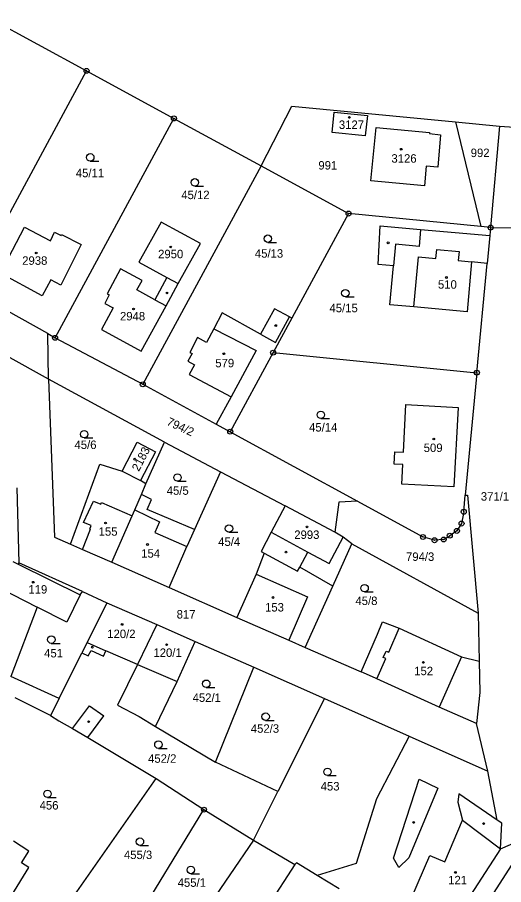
# Model space of a CAD drawing. Extents: x -735249 to -729401, y -1124843 to -1121828.
# Drawn here: x -734537.4 to -734439.6, y -1122803 to -1122628.7 of the extents above; entities that cross this region are included whole.
import ezdxf

# ---------------------------------------------------------------- set-up
doc = ezdxf.new("R2010")
doc.units = 0
for name, color, linetype in [('Vrstva 1', 7, 'Continuous'), ('Vrstva 13', 7, 'Continuous'), ('Vrstva 18', 7, 'Continuous'), ('Vrstva 19', 7, 'Continuous'), ('Vrstva 25', 7, 'Continuous'), ('Vrstva 4', 7, 'Continuous')]:
    doc.layers.add(name, color=color, linetype=linetype)

msp = doc.modelspace()

# ---------------------------------------------------------------- linework, layer by layer
at = {"layer": 'Vrstva 1'}
for points in [[(-734547.14, -1122683.19), (-734523.44, -1122639.42)], [(-734474.05, -1122651.8), (-734473.65, -1122647.74)], [(-734473.65, -1122647.74), (-734466.97, -1122648.39)], [(-734529.77, -1122693.08), (-734505.87, -1122648.98)], [(-734466.97, -1122648.39), (-734467.41, -1122652.45)], [(-734449.25, -1122649.69), (-734444.16, -1122670.72)], [(-734466.26, -1122661.51), (-734465.21, -1122650.81)], [(-734465.21, -1122650.81), (-734454.5, -1122651.83)], [(-734440.39, -1122650.54), (-734442.18, -1122670.92)], [(-734467.41, -1122652.45), (-734474.05, -1122651.8)], [(-734454.5, -1122651.83), (-734454.5, -1122652.02)], [(-734454.5, -1122652.02), (-734452.25, -1122652.3)], [(-734452.25, -1122652.3), (-734452.82, -1122658.76)], [(-734488.31, -1122658.54), (-734512.13, -1122702.42)], [(-734488.31, -1122658.54), (-734470.74, -1122668.1)], [(-734455.12, -1122658.57), (-734455.5, -1122662.53)], [(-734452.82, -1122658.76), (-734455.12, -1122658.57)], [(-734455.5, -1122662.53), (-734466.26, -1122661.51)], [(-734470.74, -1122668.1), (-734482.16, -1122689.14)], [(-734444.16, -1122670.72), (-734470.74, -1122668.1)], [(-734508.45, -1122669.82), (-734512.93, -1122677.86)], [(-734500.54, -1122674.09), (-734508.45, -1122669.82)], [(-734464.82, -1122678.34), (-734464.37, -1122670.58)], [(-734464.37, -1122670.58), (-734456.27, -1122671.28)], [(-734442.18, -1122670.92), (-734444.16, -1122670.72)], [(-734540.77, -1122680.09), (-734535.9, -1122670.83)], [(-734535.9, -1122670.83), (-734530.69, -1122673.58)], [(-734530.69, -1122673.58), (-734529.91, -1122671.87)], [(-734529.91, -1122671.87), (-734528.58, -1122672.51)], [(-734528.58, -1122672.51), (-734528.48, -1122672.34)], [(-734528.48, -1122672.34), (-734524.51, -1122674.3)], [(-734456.27, -1122671.28), (-734442.33, -1122672.48)], [(-734442.33, -1122672.48), (-734442.87, -1122678.13)], [(-734442.18, -1122670.92), (-734442.33, -1122672.48)], [(-734442.18, -1122670.92), (-734432.18, -1122671.05)], [(-734505, -1122682.19), (-734500.54, -1122674.09)], [(-734524.51, -1122674.3), (-734528.62, -1122682.51)], [(-734516.61, -1122679.23), (-734519.28, -1122684.26)], [(-734512.26, -1122681.53), (-734516.61, -1122679.23)], [(-734512.93, -1122677.86), (-734507.29, -1122680.93)], [(-734461.72, -1122678.61), (-734464.82, -1122678.34)], [(-734462.43, -1122686.42), (-734461.72, -1122678.61)], [(-734446.02, -1122677.83), (-734446.9, -1122687.85)], [(-734442.87, -1122678.13), (-734446.02, -1122677.83)], [(-734444.95, -1122700.08), (-734442.87, -1122678.13)], [(-734532.4, -1122684.64), (-734540.77, -1122680.09)], [(-734507.29, -1122680.93), (-734509.74, -1122685.41)], [(-734530.64, -1122681.41), (-734532.4, -1122684.64)], [(-734528.62, -1122682.51), (-734530.64, -1122681.41)], [(-734513.31, -1122683.44), (-734512.26, -1122681.53)], [(-734507.46, -1122686.66), (-734505, -1122682.19)], [(-734518.91, -1122684.45), (-734519.77, -1122686.17)], [(-734519.28, -1122684.26), (-734518.91, -1122684.45)], [(-734509.74, -1122685.41), (-734513.31, -1122683.44)], [(-734519.77, -1122686.17), (-734518.1, -1122687.06)], [(-734509.74, -1122685.41), (-734507.46, -1122686.66)], [(-734457.62, -1122686.86), (-734462.43, -1122686.42)], [(-734531.21, -1122692.22), (-734539.28, -1122687.73)], [(-734518.1, -1122687.06), (-734520.43, -1122691.38)], [(-734512.48, -1122695.77), (-734507.46, -1122686.66)], [(-734496.15, -1122688.07), (-734497.86, -1122691.26)], [(-734488.43, -1122692.37), (-734496.15, -1122688.07)], [(-734485.67, -1122687.24), (-734488.43, -1122692.37)], [(-734482.65, -1122688.88), (-734485.67, -1122687.24)], [(-734446.9, -1122687.85), (-734457.62, -1122686.86)], [(-734482.16, -1122689.14), (-734485.92, -1122696.06)], [(-734482.16, -1122689.14), (-734482.65, -1122688.88)], [(-734520.43, -1122691.38), (-734512.48, -1122695.77)], [(-734497.86, -1122691.26), (-734499.32, -1122693.99)], [(-734531.09, -1122701.37), (-734531.21, -1122692.22)], [(-734531.21, -1122692.22), (-734529.77, -1122693.08)], [(-734529.77, -1122693.08), (-734512.13, -1122702.42)], [(-734501.11, -1122693.03), (-734502.64, -1122696.01)], [(-734499.32, -1122693.99), (-734501.11, -1122693.03)], [(-734531.09, -1122701.37), (-734539.43, -1122696.77)], [(-734502.22, -1122696.24), (-734503.07, -1122697.78)], [(-734502.64, -1122696.01), (-734502.22, -1122696.24)], [(-734485.92, -1122696.06), (-734494.54, -1122711.94)], [(-734485.92, -1122696.06), (-734444.95, -1122700.08)], [(-734503.07, -1122697.78), (-734501.74, -1122698.5)], [(-734501.74, -1122698.5), (-734502.78, -1122700.43)], [(-734502.78, -1122700.43), (-734494.38, -1122704.95)], [(-734444.95, -1122700.08), (-734447.27, -1122724.73)], [(-734507.74, -1122714.08), (-734531.09, -1122701.37)], [(-734531.09, -1122701.37), (-734529.88, -1122733.15)], [(-734512.13, -1122702.42), (-734497.35, -1122710.42)], [(-734494.38, -1122704.95), (-734497.35, -1122710.42)], [(-734459.7, -1122716.07), (-734459.22, -1122706.49)], [(-734459.22, -1122706.49), (-734448.71, -1122707.11)], [(-734448.71, -1122707.11), (-734449.57, -1122723.04)], [(-734497.35, -1122710.42), (-734494.54, -1122711.94)], [(-734494.54, -1122711.94), (-734468.96, -1122725.91)], [(-734516.28, -1122719.89), (-734513.27, -1122714.06)], [(-734513.27, -1122714.06), (-734509.58, -1122715.96)], [(-734511.54, -1122722.39), (-734507.74, -1122714.08)], [(-734507.74, -1122714.08), (-734496.52, -1122720.03)], [(-734509.58, -1122715.96), (-734512.57, -1122721.75)], [(-734461.55, -1122718.45), (-734461.43, -1122715.99)], [(-734461.43, -1122715.99), (-734459.7, -1122716.07)], [(-734526.64, -1122734.56), (-734520.75, -1122718.45)], [(-734520.75, -1122718.45), (-734516.28, -1122719.89)], [(-734459.82, -1122718.53), (-734461.55, -1122718.45)], [(-734460.02, -1122722.48), (-734459.82, -1122718.53)], [(-734516.28, -1122719.89), (-734512.57, -1122721.75)], [(-734496.52, -1122720.03), (-734501.72, -1122731.57)], [(-734496.52, -1122720.03), (-734483.48, -1122726.85)], [(-734511.54, -1122722.39), (-734512.57, -1122721.75)], [(-734512.39, -1122724.55), (-734511.54, -1122722.39)], [(-734449.57, -1122723.04), (-734460.02, -1122722.48)], [(-734537.44, -1122723.23), (-734537.08, -1122738.3)], [(-734513.7, -1122727.63), (-734512.39, -1122724.55)], [(-734510.41, -1122725.56), (-734512.39, -1122724.55)], [(-734447.58, -1122728.03), (-734447.27, -1122724.73)], [(-734447.27, -1122724.73), (-734446.8, -1122724.71)], [(-734446.8, -1122724.71), (-734444.66, -1122748.41)], [(-734511.28, -1122727.58), (-734510.41, -1122725.56)], [(-734472.72, -1122726.12), (-734473.53, -1122732.13)], [(-734468.96, -1122725.91), (-734472.72, -1122726.12)], [(-734468.96, -1122725.91), (-734455.79, -1122733.1)], [(-734514.27, -1122728.86), (-734513.7, -1122727.63)], [(-734501.72, -1122731.57), (-734511.28, -1122727.58)], [(-734483.48, -1122726.85), (-734486.29, -1122732.15)], [(-734473.53, -1122732.13), (-734483.48, -1122726.85)], [(-734447.58, -1122728.03), (-734448.03, -1122730.4)], [(-734518.34, -1122738.18), (-734514.27, -1122728.86)], [(-734501.72, -1122731.57), (-734503.27, -1122735)], [(-734448.03, -1122730.4), (-734448.96, -1122731.87)], [(-734529.88, -1122733.15), (-734526.64, -1122734.56)], [(-734486.29, -1122732.15), (-734488.35, -1122736.04)], [(-734471.86, -1122733.15), (-734473.53, -1122732.13)], [(-734470.09, -1122734.45), (-734471.86, -1122733.15)], [(-734453.45, -1122733.75), (-734455.79, -1122733.1)], [(-734451.63, -1122733.61), (-734450.39, -1122732.84)], [(-734448.96, -1122731.87), (-734450.39, -1122732.84)], [(-734526.64, -1122734.56), (-734524.29, -1122735.59)], [(-734506.84, -1122743.27), (-734503.27, -1122735)], [(-734473.93, -1122742.99), (-734470.09, -1122734.45)], [(-734470.09, -1122734.45), (-734444.66, -1122748.41)], [(-734451.63, -1122733.61), (-734453.45, -1122733.75)], [(-734524.29, -1122735.59), (-734518.34, -1122738.18)], [(-734487.75, -1122736.36), (-734489.34, -1122740.55)], [(-734488.35, -1122736.04), (-734487.75, -1122736.36)], [(-734487.75, -1122736.36), (-734481, -1122739.99)], [(-734538.26, -1122738.04), (-734537.07, -1122738.63)], [(-734537.07, -1122738.63), (-734537.08, -1122738.3)], [(-734524.26, -1122744.09), (-734537.08, -1122738.3)], [(-734518.34, -1122738.18), (-734506.84, -1122743.27)], [(-734481, -1122739.99), (-734480.56, -1122739.17)], [(-734473.93, -1122742.99), (-734480.56, -1122739.17)], [(-734489.34, -1122740.55), (-734493.22, -1122749.27)], [(-734506.84, -1122743.27), (-734493.22, -1122749.27)], [(-734479.46, -1122755.29), (-734473.93, -1122742.99)], [(-734524.7, -1122744.76), (-734527.4, -1122750.2)], [(-734524.7, -1122744.76), (-734524.26, -1122744.09)], [(-734524.26, -1122744.09), (-734519.36, -1122746.31)], [(-734533.37, -1122747.19), (-734538.69, -1122761.14)], [(-734527.4, -1122750.2), (-734533.37, -1122747.19)], [(-734519.36, -1122746.31), (-734523.34, -1122754.31)], [(-734519.36, -1122746.31), (-734509.3, -1122750.71)], [(-734444.66, -1122748.41), (-734444.48, -1122758.07)], [(-734509.3, -1122750.71), (-734513.22, -1122758.7)], [(-734509.3, -1122750.71), (-734501.6, -1122754.11)], [(-734493.22, -1122749.27), (-734482.76, -1122753.85)], [(-734464.91, -1122752.65), (-734463.94, -1122750.16)], [(-734463.94, -1122750.16), (-734460.57, -1122751.42)], [(-734468.22, -1122760.22), (-734464.91, -1122752.65)], [(-734460.57, -1122751.42), (-734448.03, -1122757.19)], [(-734523.34, -1122754.31), (-734524.37, -1122756.37)], [(-734505.24, -1122762.17), (-734501.6, -1122754.11)], [(-734501.6, -1122754.11), (-734489.82, -1122759.27)], [(-734482.76, -1122753.85), (-734479.46, -1122755.29)], [(-734523.12, -1122756.99), (-734522.54, -1122755.93)], [(-734522.54, -1122755.93), (-734520.02, -1122757.03)], [(-734520.02, -1122757.03), (-734519.55, -1122755.96)], [(-734513.22, -1122758.7), (-734519.55, -1122755.96)], [(-734479.46, -1122755.29), (-734468.22, -1122760.22)], [(-734528.92, -1122765.53), (-734524.37, -1122756.37)], [(-734524.37, -1122756.37), (-734523.12, -1122756.99)], [(-734448.03, -1122757.19), (-734444.48, -1122758.07)], [(-734513.22, -1122758.7), (-734517.23, -1122766.9)], [(-734497.54, -1122778.33), (-734489.82, -1122759.27)], [(-734489.82, -1122759.27), (-734475.58, -1122765.57)], [(-734444.48, -1122758.07), (-734444.36, -1122764.34)], [(-734528.92, -1122765.53), (-734538.69, -1122761.14)], [(-734465.36, -1122761.48), (-734468.22, -1122760.22)], [(-734509.55, -1122771.18), (-734505.24, -1122762.17)], [(-734465.05, -1122761.64), (-734465.36, -1122761.48)], [(-734452.54, -1122767.3), (-734465.05, -1122761.64)], [(-734444.36, -1122764.34), (-734445, -1122770.59)], [(-734530.7, -1122768.99), (-734537.79, -1122765.42)], [(-734528.92, -1122765.53), (-734530.7, -1122768.99)], [(-734475.58, -1122765.57), (-734485, -1122784.28)], [(-734475.58, -1122765.57), (-734458.58, -1122773.14)], [(-734517.23, -1122766.9), (-734512.89, -1122769.19)], [(-734445, -1122770.59), (-734452.54, -1122767.3)], [(-734530.7, -1122768.99), (-734528.99, -1122770.02)], [(-734528.99, -1122770.02), (-734526.26, -1122771.61)], [(-734512.89, -1122769.19), (-734509.55, -1122771.18)], [(-734526.26, -1122771.61), (-734523.19, -1122773.42)], [(-734509.55, -1122771.18), (-734497.54, -1122778.33)], [(-734442.75, -1122780.19), (-734445, -1122770.59)], [(-734523.19, -1122773.42), (-734509.45, -1122781.62)], [(-734458.58, -1122773.14), (-734465.14, -1122785.71)], [(-734458.58, -1122773.14), (-734442.75, -1122780.19)], [(-734485, -1122784.28), (-734497.54, -1122778.33)], [(-734440.86, -1122789.99), (-734442.75, -1122780.19)], [(-734525.86, -1122805.12), (-734509.45, -1122781.62)], [(-734509.45, -1122781.62), (-734499.83, -1122787.9)], [(-734489.86, -1122794.01), (-734485, -1122784.28)], [(-734465.14, -1122785.71), (-734469.23, -1122798.73)], [(-734514.83, -1122812.39), (-734499.83, -1122787.9)], [(-734499.83, -1122787.9), (-734489.86, -1122794.01)], [(-734439.9, -1122790.59), (-734440.86, -1122789.99)], [(-734440.18, -1122795.78), (-734439.9, -1122790.59)], [(-734535.06, -1122796.27), (-734538.14, -1122794.21)], [(-734489.86, -1122794.01), (-734504.18, -1122814.91)], [(-734489.86, -1122794.01), (-734481.54, -1122798.9)], [(-734440.18, -1122795.78), (-734436.67, -1122794.23)], [(-734536.51, -1122798.61), (-734535.06, -1122796.27)], [(-734440.18, -1122795.78), (-734450.06, -1122810.97)], [(-734538.46, -1122805.1), (-734535.06, -1122799.51)], [(-734535.06, -1122799.51), (-734536.51, -1122798.61)], [(-734481.54, -1122798.9), (-734486.88, -1122807.13)], [(-734481.22, -1122798.56), (-734481.54, -1122798.9)], [(-734477.06, -1122801.11), (-734481.22, -1122798.56)], [(-734469.23, -1122798.73), (-734477.06, -1122801.11)], [(-734472.65, -1122803.81), (-734477.06, -1122801.11)]]:
    msp.add_lwpolyline(points, dxfattribs=at)
at = {"layer": 'Vrstva 13'}
for points in [[(-734543.2, -1122628.67), (-734523.44, -1122639.42)], [(-734523.44, -1122639.42), (-734505.87, -1122648.98)], [(-734488.31, -1122658.54), (-734482.18, -1122646.53)], [(-734482.18, -1122646.53), (-734449.25, -1122649.69)], [(-734505.87, -1122648.98), (-734488.31, -1122658.54)], [(-734449.25, -1122649.69), (-734440.39, -1122650.54)], [(-734440.39, -1122650.54), (-734430.4, -1122651.21)]]:
    msp.add_lwpolyline(points, dxfattribs=at)
at = {"layer": 'Vrstva 25'}
for points in [[(-734522.7, -1122657.56), (-734520.95, -1122657.56)], [(-734501.66, -1122662.59), (-734499.91, -1122662.59)], [(-734486.99, -1122673.9), (-734485.24, -1122673.9)], [(-734471.4, -1122684.86), (-734469.65, -1122684.86)], [(-734476.32, -1122709.3), (-734474.57, -1122709.3)], [(-734523.92, -1122713.2), (-734522.17, -1122713.2)], [(-734505.15, -1122721.89), (-734503.4, -1122721.89)], [(-734494.8, -1122732.16), (-734493.05, -1122732.16)], [(-734467.53, -1122744.13), (-734465.78, -1122744.13)], [(-734530.53, -1122754.48), (-734528.78, -1122754.48)], [(-734499.37, -1122763.35), (-734497.62, -1122763.35)], [(-734487.43, -1122769.96), (-734485.68, -1122769.96)], [(-734508.99, -1122775.58), (-734507.24, -1122775.58)], [(-734474.98, -1122781.05), (-734473.23, -1122781.05)], [(-734531.29, -1122785.47), (-734529.54, -1122785.47)], [(-734512.71, -1122795.09), (-734510.96, -1122795.09)], [(-734502.48, -1122800.77), (-734500.73, -1122800.77)]]:
    msp.add_lwpolyline(points, dxfattribs=at)
for centre, radius in [((-734523.44, -1122639.42), 0.5), ((-734523.44, -1122639.42), 0.032), ((-734505.87, -1122648.98), 0.5), ((-734505.87, -1122648.98), 0.032), ((-734470.59, -1122648.79), 0.175), ((-734460.16, -1122655.18), 0.175), ((-734522.7, -1122656.81), 0.75), ((-734501.66, -1122661.84), 0.75), ((-734470.74, -1122668.1), 0.5), ((-734470.74, -1122668.1), 0.032), ((-734442.18, -1122670.92), 0.5), ((-734486.99, -1122673.15), 0.75), ((-734442.18, -1122670.92), 0.032), ((-734462.78, -1122673.98), 0.175), ((-734533.56, -1122676.02), 0.175), ((-734506.52, -1122674.82), 0.175), ((-734451.07, -1122680.95), 0.175), ((-734507.27, -1122684.06), 0.175), ((-734471.4, -1122684.11), 0.75), ((-734513.98, -1122687.28), 0.175), ((-734485.39, -1122690.61), 0.175), ((-734529.77, -1122693.08), 0.5), ((-734529.77, -1122693.08), 0.032), ((-734495.83, -1122696.28), 0.175), ((-734485.92, -1122696.06), 0.5), ((-734485.92, -1122696.06), 0.032), ((-734444.95, -1122700.08), 0.5), ((-734444.95, -1122700.08), 0.032), ((-734512.13, -1122702.42), 0.5), ((-734512.13, -1122702.42), 0.032), ((-734476.32, -1122708.55), 0.75), ((-734523.92, -1122712.45), 0.75), ((-734494.54, -1122711.94), 0.5), ((-734494.54, -1122711.94), 0.032), ((-734453.62, -1122713.42), 0.175), ((-734513.76, -1122717.47), 0.175), ((-734505.15, -1122721.14), 0.75), ((-734447.58, -1122728.03), 0.5), ((-734447.58, -1122728.03), 0.032), ((-734448.03, -1122730.4), 0.5), ((-734519.61, -1122730.3), 0.175), ((-734494.8, -1122731.41), 0.75), ((-734479.1, -1122731.08), 0.175), ((-734448.96, -1122731.87), 0.5), ((-734448.03, -1122730.4), 0.032), ((-734455.79, -1122733.1), 0.5), ((-734455.79, -1122733.1), 0.032), ((-734453.45, -1122733.75), 0.5), ((-734451.63, -1122733.61), 0.5), ((-734450.39, -1122732.84), 0.5), ((-734450.39, -1122732.84), 0.032), ((-734448.96, -1122731.87), 0.032), ((-734511.18, -1122734.61), 0.175), ((-734453.45, -1122733.75), 0.032), ((-734451.63, -1122733.61), 0.032), ((-734483.34, -1122736.14), 0.175), ((-734534.16, -1122742.2), 0.175), ((-734467.53, -1122743.38), 0.75), ((-734485.95, -1122745.27), 0.175), ((-734516.3, -1122750.68), 0.175), ((-734530.53, -1122753.73), 0.75), ((-734522.28, -1122755.25), 0.175), ((-734507.34, -1122754.75), 0.175), ((-734455.71, -1122758.31), 0.175), ((-734499.37, -1122762.6), 0.75), ((-734523.02, -1122770.22), 0.175), ((-734487.43, -1122769.21), 0.75), ((-734508.99, -1122774.83), 0.75), ((-734474.98, -1122780.3), 0.75), ((-734531.29, -1122784.72), 0.75), ((-734499.83, -1122787.9), 0.5), ((-734499.83, -1122787.9), 0.032), ((-734457.65, -1122790.47), 0.175), ((-734443.59, -1122790.7), 0.175), ((-734512.71, -1122794.34), 0.75), ((-734502.48, -1122800.02), 0.75), ((-734449.26, -1122800.51), 0.175)]:
    msp.add_circle(centre, radius, dxfattribs=at)
at = {"layer": 'Vrstva 4'}
for points in [[(-734456.27, -1122671.28), (-734456.53, -1122674.75)], [(-734461.34, -1122674.25), (-734461.72, -1122678.61)], [(-734456.53, -1122674.75), (-734461.34, -1122674.25)], [(-734453.19, -1122677.15), (-734453.02, -1122675.32)], [(-734453.02, -1122675.32), (-734448.54, -1122675.74)], [(-734448.54, -1122675.74), (-734448.71, -1122677.57)], [(-734457.62, -1122686.86), (-734456.71, -1122676.78)], [(-734456.71, -1122676.78), (-734453.19, -1122677.15)], [(-734448.71, -1122677.57), (-734446.02, -1122677.83)], [(-734507.29, -1122680.93), (-734505, -1122682.19)], [(-734485.43, -1122694), (-734482.65, -1122688.88)], [(-734497.86, -1122691.26), (-734489.35, -1122695.61)], [(-734488.43, -1122692.37), (-734485.43, -1122694)], [(-734489.35, -1122695.61), (-734494.38, -1122704.95)], [(-734524.03, -1122730.17), (-734522.06, -1122725.88)], [(-734522.06, -1122725.88), (-734520.6, -1122726.51)], [(-734520.6, -1122726.51), (-734520.46, -1122726.19)], [(-734520.46, -1122726.19), (-734514.27, -1122728.86)], [(-734513.7, -1122727.63), (-734508.78, -1122730.04)], [(-734508.78, -1122730.04), (-734509.72, -1122732.22)], [(-734524.29, -1122735.59), (-734522.67, -1122731.56)], [(-734522.52, -1122730.78), (-734524.03, -1122730.17)], [(-734522.81, -1122731.5), (-734522.52, -1122730.78)], [(-734522.67, -1122731.56), (-734522.81, -1122731.5)], [(-734509.72, -1122732.22), (-734503.27, -1122735)], [(-734486.29, -1122732.15), (-734478.92, -1122736.13)], [(-734474.68, -1122738.4), (-734471.86, -1122733.15)], [(-734480.56, -1122739.17), (-734478.92, -1122736.13)], [(-734478.92, -1122736.13), (-734474.68, -1122738.4)], [(-734537.07, -1122738.63), (-734524.7, -1122744.76)], [(-734489.34, -1122740.55), (-734479.01, -1122745.12)], [(-734540.85, -1122743.41), (-734533.37, -1122747.19)], [(-734479.01, -1122745.12), (-734482.76, -1122753.85)], [(-734462.68, -1122756.24), (-734460.57, -1122751.42)], [(-734523.34, -1122754.31), (-734519.55, -1122755.96)], [(-734463.76, -1122757.29), (-734463.2, -1122756.02)], [(-734463.2, -1122756.02), (-734462.68, -1122756.24)], [(-734465.05, -1122761.64), (-734463.24, -1122757.52)], [(-734463.24, -1122757.52), (-734463.76, -1122757.29)], [(-734448.03, -1122757.19), (-734452.54, -1122767.3)], [(-734513.22, -1122758.7), (-734505.24, -1122762.17)], [(-734526.26, -1122771.61), (-734522.88, -1122767.02)], [(-734522.88, -1122767.02), (-734519.94, -1122769.07)], [(-734523.19, -1122773.42), (-734519.94, -1122769.07)], [(-734461.73, -1122797.64), (-734456.57, -1122781.75)], [(-734456.57, -1122781.75), (-734452.82, -1122783.58)], [(-734452.82, -1122783.58), (-734458.64, -1122797.57)], [(-734448.56, -1122784.72), (-734448.8, -1122786.41)], [(-734440.86, -1122789.99), (-734448.56, -1122784.72)], [(-734448.8, -1122786.41), (-734447.84, -1122790)], [(-734451.4, -1122798.36), (-734447.84, -1122790)], [(-734447.84, -1122790), (-734440.18, -1122795.78)], [(-734460.67, -1122799.53), (-734461.73, -1122797.64)], [(-734458.64, -1122797.57), (-734460.67, -1122799.53)], [(-734458.04, -1122805.47), (-734454.38, -1122797.09)], [(-734454.38, -1122797.09), (-734451.4, -1122798.36)], [(-734436.74, -1122797.06), (-734445.3, -1122810.35)]]:
    msp.add_lwpolyline(points, dxfattribs=at)

# ---------------------------------------------------------------- texts
at = {"layer": 'Vrstva 18'}
for s, p in [('992', (-734446.19, -1122656.75)), ('991', (-734476.82, -1122659.26)), ('45/11', (-734525.6, -1122660.8)), ('45/12', (-734504.39, -1122665.2)), ('45/13', (-734489.59, -1122676.97)), ('45/15', (-734474.59, -1122687.94)), ('45/14', (-734478.69, -1122711.91)), ('45/6', (-734525.87, -1122715.42)), ('45/5', (-734507.32, -1122724.62)), ('371/1', (-734444.15, -1122725.8)), ('45/4', (-734496.97, -1122734.9)), ('794/3', (-734459.2, -1122737.91)), ('45/8', (-734469.37, -1122746.78)), ('817', (-734505.32, -1122749.49)), ('451', (-734531.97, -1122757.3)), ('452/1', (-734502.11, -1122766.25)), ('452/3', (-734490.41, -1122772.45)), ('452/2', (-734511.07, -1122778.48)), ('453', (-734476.36, -1122784.05)), ('456', (-734532.88, -1122787.88)), ('455/3', (-734515.93, -1122797.83)), ('455/1', (-734505.12, -1122803.41))]:
    msp.add_text(s, height=1.7, dxfattribs=at).set_placement(p)
msp.add_text('794/2', height=1.7, rotation=335.00266, dxfattribs=at).set_placement((-734507.485, -1122710.514))
at = {"layer": 'Vrstva 19'}
for s, p in [('3127', (-734472.7, -1122651.1)), ('3126', (-734462.13, -1122657.88)), ('2950', (-734509.05, -1122677.08)), ('2938', (-734536.38, -1122678.4)), ('510', (-734452.77, -1122683.2)), ('2948', (-734516.72, -1122689.58)), ('579', (-734497.55, -1122699)), ('509', (-734455.64, -1122716.03)), ('155', (-734521.01, -1122732.85)), ('2993', (-734481.67, -1122733.49)), ('154', (-734512.45, -1122737.26)), ('119', (-734535.14, -1122744.48)), ('153', (-734487.54, -1122748.08)), ('120/2', (-734519.28, -1122753.42)), ('120/1', (-734509.99, -1122757.2)), ('152', (-734457.55, -1122760.88)), ('121', (-734450.72, -1122802.91))]:
    msp.add_text(s, height=1.7, dxfattribs=at).set_placement(p)
msp.add_text('2183', height=1.7, rotation=62.8005, dxfattribs=at).set_placement((-734512.926, -1122720.061))

doc.saveas('drawing.dxf')
